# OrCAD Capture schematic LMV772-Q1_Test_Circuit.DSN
size A; title: LMV771/LMV772/LMV772Q/LMV774 Single/Dual/Quad, Low; rev: 1.3; note: Datasheet: SNOSA04F   EVM: N/A
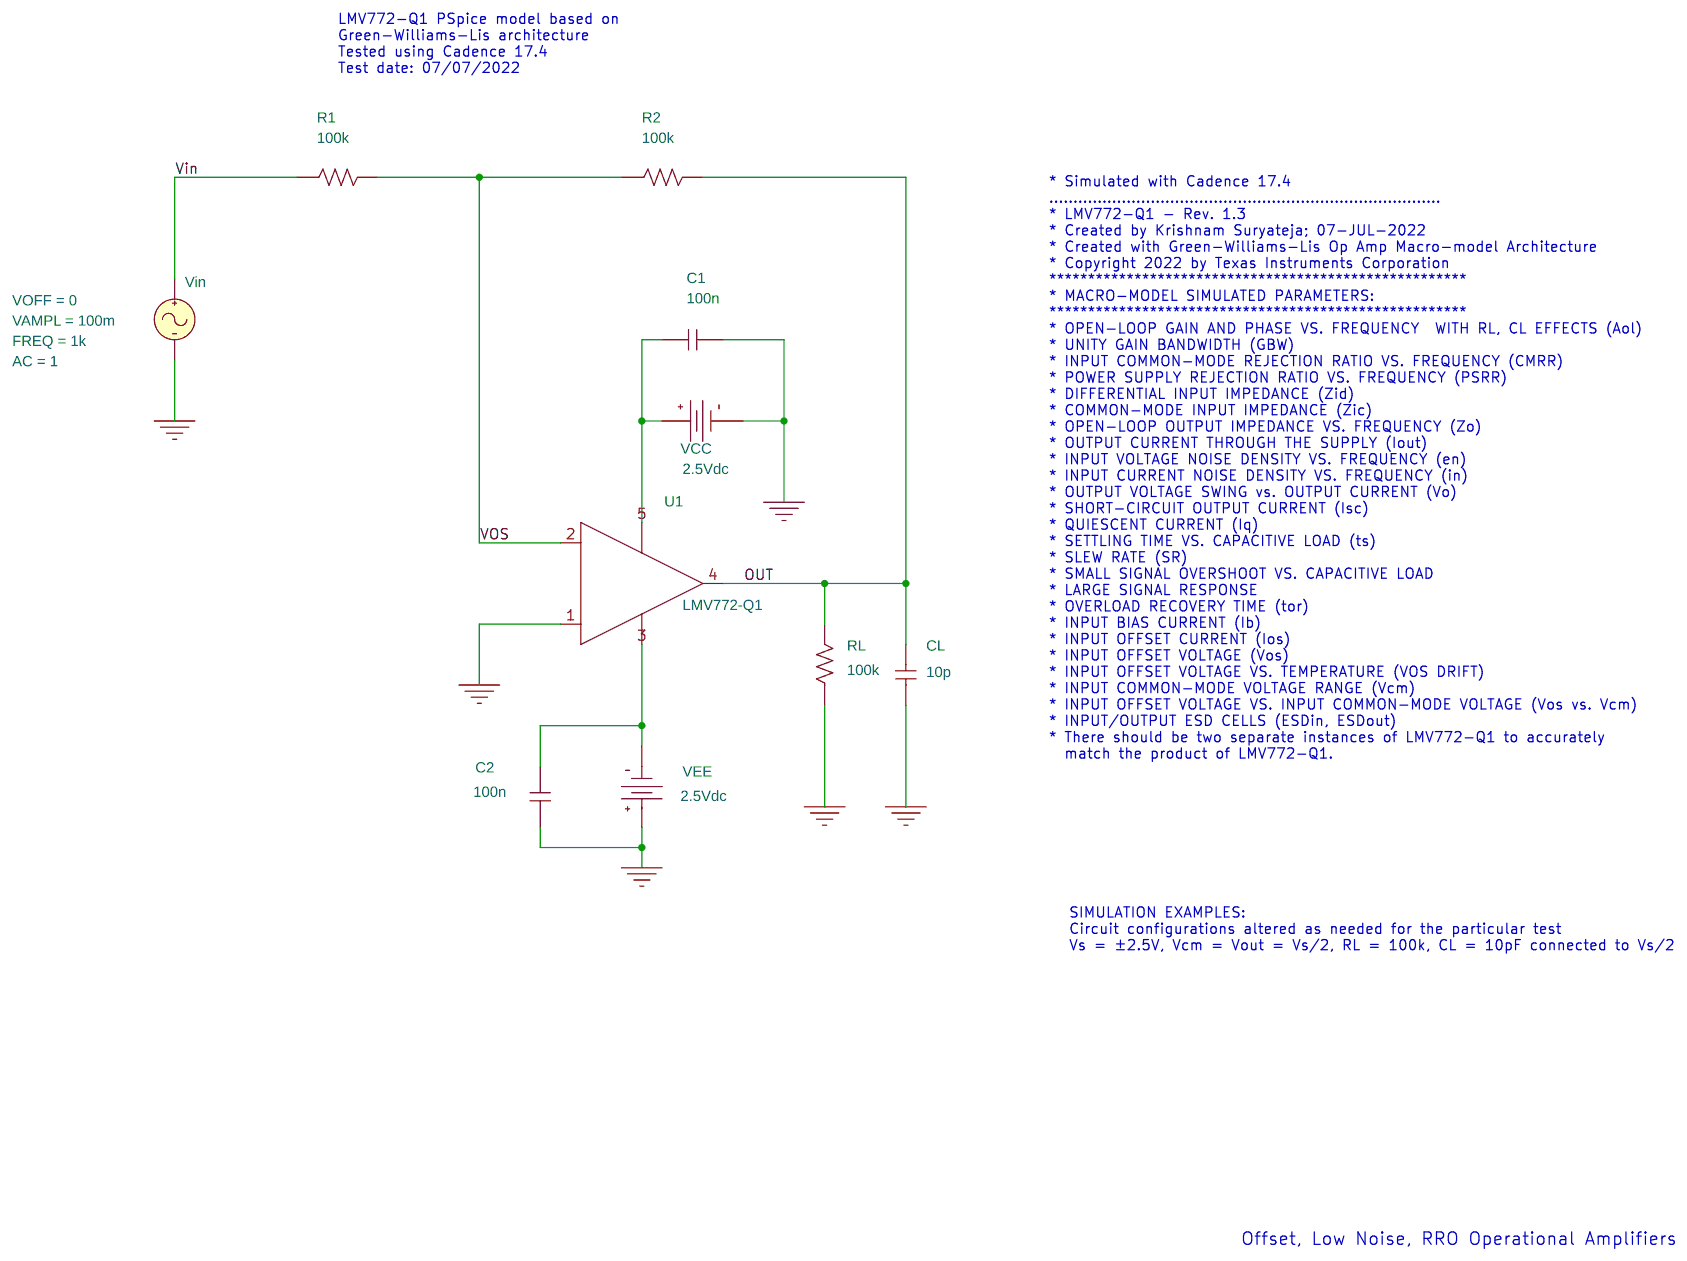
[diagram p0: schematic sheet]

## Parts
C1  100n  [cap196]
C2  100n  [cap196]
CL  10p  [cap196]
R1  100k  [AXRC05]
R2  100k  [AXRC05]
RL  100k  [AXRC05]
U1  LMV772-Q1
VCC  VDC
VEE  VDC
Vin  VSIN

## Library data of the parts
C1 C2 CL = C
R1 R2 RL = R
U1 = LMV772-Q1
VCC VEE = VDC: DC: 2.5Vdc
Vin = VSIN: AC: 1; FREQ: 1k; VAMPL: 100m; VOFF: 0

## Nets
Vin: R1.1 Vin.1(+)
0: C1.2 C2.1 CL.2 RL.1 U1.1(+) VCC.1(-) VEE.0(+) Vin.2(-)
OUT: CL.1 R2.2 RL.2 U1.4(OUT)
VOS: R1.2 R2.1 U1.2(-)
N27303: C1.1 U1.5(V+) VCC.0(+)
N27354: C2.2 U1.3(V-) VEE.1(-)

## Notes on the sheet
- LMV772-Q1 PSpice model based on
  Green-Williams-Lis architecture
  Tested using Cadence 17.4
  Test date: 07/07/2022
- * Simulated with Cadence 17.4
  .................................................................................
  * LMV772-Q1 - Rev. 1.3
  * Created by Krishnam Suryateja; 07-JUL-2022
  * Created with Green-Williams-Lis Op Amp Macro-model Architecture
  * Copyright 2022 by Texas Instruments Corporation
  ******************************************************
  * MACRO-MODEL SIMULATED PARAMETERS:
  ******************************************************
  * OPEN-LOOP GAIN AND PHASE VS. FREQUENCY  WITH RL, CL EFFECTS (Aol)
  * UNITY GAIN BANDWIDTH (GBW)
  * INPUT COMMON-MODE REJECTION RATIO VS. FREQUENCY (CMRR)
  * POWER SUPPLY REJECTION RATIO VS. FREQUENCY (PSRR)
  * DIFFERENTIAL INPUT IMPEDANCE (Zid)
  * COMMON-MODE INPUT IMPEDANCE (Zic)
  * OPEN-LOOP OUTPUT IMPEDANCE VS. FREQUENCY (Zo)
  * OUTPUT CURRENT THROUGH THE SUPPLY (Iout)
  * INPUT VOLTAGE NOISE DENSITY VS. FREQUENCY (en)
  * INPUT CURRENT NOISE DENSITY VS. FREQUENCY (in)
  * OUTPUT VOLTAGE SWING vs. OUTPUT CURRENT (Vo)
  * SHORT-CIRCUIT OUTPUT CURRENT (Isc)
  * QUIESCENT CURRENT (Iq)
  * SETTLING TIME VS. CAPACITIVE LOAD (ts)
  * SLEW RATE (SR)
  * SMALL SIGNAL OVERSHOOT VS. CAPACITIVE LOAD
  * LARGE SIGNAL RESPONSE
  * OVERLOAD RECOVERY TIME (tor)
  * INPUT BIAS CURRENT (Ib)
  * INPUT OFFSET CURRENT (Ios)
  * INPUT OFFSET VOLTAGE (Vos)
  * INPUT OFFSET VOLTAGE VS. TEMPERATURE (VOS DRIFT)
  * INPUT COMMON-MODE VOLTAGE RANGE (Vcm)
  * INPUT OFFSET VOLTAGE VS. INPUT COMMON-MODE VOLTAGE (Vos vs. Vcm)
  * INPUT/OUTPUT ESD CELLS (ESDin, ESDout)
  * There should be two separate instances of LMV772-Q1 to accurately
    match the product of LMV772-Q1.
- SIMULATION EXAMPLES:
  Circuit configurations altered as needed for the particular test
  Vs = ±2.5V, Vcm = Vout = Vs/2, RL = 100k, CL = 10pF connected to Vs/2
- Offset, Low Noise, RRO Operational Amplifiers
